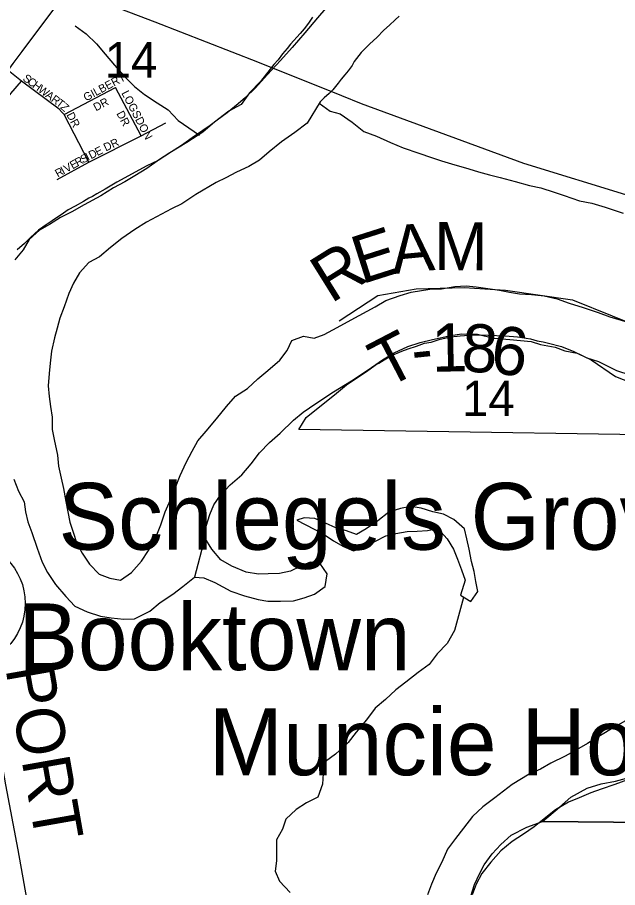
# Model space of a CAD drawing. Extents: x 1588073 to 2013523, y 1090242 to 1357120.
# Drawn here: x 1801898 to 1805645, y 1233367 to 1238801 of the extents above; entities that cross this region are included whole.
import ezdxf

# ---------------------------------------------------------------- set-up
doc = ezdxf.new("R2010")
doc.units = 0
for name, color, linetype in [('GM_X_County_Road', 7, 'Continuous'), ('GM_X_County_Road_Text', 7, 'Continuous'), ('GM_X_Interstate_Route', 7, 'Continuous'), ('GM_X_Major_River', 7, 'Continuous'), ('GM_X_Minor_River', 7, 'Continuous'), ('GM_X_Section', 7, 'Continuous'), ('GM_X_Section_Text', 7, 'Continuous'), ('GM_X_State_Route', 7, 'Continuous'), ('GM_X_Township_Road', 7, 'Continuous'), ('GM_X_Township_Road_Text', 7, 'Continuous'), ('GM_X_Township_Subdivision', 7, 'Continuous'), ('GM_X_Township_Subdivision_Text', 7, 'Continuous'), ('GM_X_Unincorporated', 7, 'Continuous'), ('GM_X_Unincorporated_Text', 7, 'Continuous')]:
    doc.layers.add(name, color=color, linetype=linetype)

msp = doc.modelspace()

# ---------------------------------------------------------------- linework, layer by layer
at = {"layer": 'GM_X_County_Road'}
for points in [[(1801278.3, 1237540.5), (1801476.7, 1237816.7), (1801857.4, 1238326), (1801923.8, 1238403.2), (1801839.7, 1238469.3)], [(1802090.5, 1232551.8), (1801902.1, 1233602.3), (1801826.4, 1234009.2), (1801770.7, 1234309.1), (1801713.5, 1234650.5), (1801537.5, 1235644.9), (1801253.4, 1237221.4), (1801246, 1237308.3), (1801251, 1237387.8), (1801278.3, 1237540.5)]]:
    msp.add_lwpolyline(points, dxfattribs=at)
at = {"layer": 'GM_X_Interstate_Route'}
for points in [[(1802220, 1238978.5), (1802756.8, 1238772.7), (1803397.5, 1238524.1), (1803921.3, 1238312.7)], [(1803921.3, 1238312.7), (1804043.4, 1238263.4), (1805058.6, 1237889.5), (1806385.8, 1237483.6), (1807153.2, 1237292.6), (1807255.1, 1237267), (1809826, 1236635.8), (1811204.6, 1236296.8), (1811922.8, 1236120.9), (1812389.9, 1236007.7), (1815154.9, 1235335.1), (1815934.8, 1235141.8), (1817359, 1234792.9), (1818064, 1234608.7), (1818464, 1234495.1), (1818935.1, 1234349.5), (1819197.3, 1234267.7)]]:
    msp.add_lwpolyline(points, dxfattribs=at)
at = {"layer": 'GM_X_Major_River'}
msp.add_line((1803067.9, 1235551.4), (1803003, 1235306.4), dxfattribs=at)
for points in [[(1803740.1, 1238801.8), (1803715.3, 1238764.1), (1803688.5, 1238728.5), (1803663.9, 1238700.8), (1803602.5, 1238633.6), (1803581.9, 1238605.8), (1803553.2, 1238572.2), (1803526.4, 1238536.6), (1803499.8, 1238506.9)], [(1804280.7, 1238807.7), (1804256.2, 1238786.1), (1804221.4, 1238752.6), (1804184.7, 1238721.1), (1804141.7, 1238675.7), (1804098.8, 1238636.3), (1804068.1, 1238604.7), (1804043.6, 1238581.1), (1804000.4, 1238525.6), (1803987.9, 1238499.7), (1803963.2, 1238468), (1803942.7, 1238442.3), (1803920.1, 1238414.6), (1803901.6, 1238390.8), (1803866.7, 1238349.2), (1803844.2, 1238325.6), (1803813.5, 1238298), (1803789, 1238274.3)], [(1803499.8, 1238506.9), (1803415.5, 1238400), (1803347.9, 1238328.9), (1803294.4, 1238257.5), (1803217.3, 1238214.8), (1803127.7, 1238146.1), (1803056.2, 1238083.1), (1802956.7, 1238018.7), (1802849, 1237954.4), (1802786, 1237913.4), (1802706.6, 1237856.6), (1802631.5, 1237811.8), (1802568.6, 1237774.8), (1802497.5, 1237735.9), (1802418.3, 1237687.2), (1802314.9, 1237630.8), (1802237.7, 1237586.1), (1802166.8, 1237551.2), (1802097.7, 1237508.3), (1802036.8, 1237471.3), (1801971.4, 1237414.2), (1801934.1, 1237348.6), (1801882.8, 1237287.3)], [(1803789, 1238274.3), (1803706.2, 1238139.2), (1803630.9, 1238082.4), (1803547.5, 1238023.6), (1803470, 1237960.8), (1803408.8, 1237909.7), (1803341.8, 1237870.7), (1803266.8, 1237834), (1803199.9, 1237799.1), (1803139.1, 1237770.1), (1803011.2, 1237694.1), (1802923.8, 1237637.4), (1802860.9, 1237604.5), (1802704.8, 1237523), (1802631.6, 1237476.1), (1802550.2, 1237419.4), (1802478.9, 1237364.4), (1802409.6, 1237305.5), (1802344.7, 1237270.5), (1802285.2, 1237205.3), (1802247.9, 1237141.7), (1802218.7, 1237075.9), (1802189.1, 1236994.1), (1802163.7, 1236922.2), (1802146.5, 1236860.2), (1802129.4, 1236800.2), (1802111.8, 1236716.1), (1802102.5, 1236641.9), (1802095.3, 1236577.8), (1802089.9, 1236499.5), (1802096.8, 1236433), (1802103.7, 1236370.6), (1802114.6, 1236304.1), (1802115.3, 1236227.7), (1802128.2, 1236165.1), (1802148.6, 1236066.3), (1802155.4, 1235997.8), (1802170.2, 1235923.1), (1802185.1, 1235858.6), (1802199.7, 1235777.9), (1802225.6, 1235648.8), (1802246.6, 1235586.1), (1802267.6, 1235521.3), (1802302.6, 1235456.4), (1802347.6, 1235387.2), (1802408.7, 1235323.7), (1802474.6, 1235300.4), (1802540.7, 1235287.1), (1802609.9, 1235334), (1802673.4, 1235405.2), (1802716.8, 1235472.7), (1802760.3, 1235548.2), (1802793.9, 1235632), (1802819.5, 1235713.9), (1802853, 1235787.7), (1802882.4, 1235861.5), (1802913.9, 1235941.3), (1802951.5, 1236021), (1802988.9, 1236092.6), (1803024.2, 1236156.3), (1803075.5, 1236217.6), (1803141.2, 1236294.8), (1803202.9, 1236372), (1803260.2, 1236435.2), (1803335.4, 1236484), (1803398.8, 1236543.1), (1803462, 1236596.2), (1803535.5, 1236661.2), (1803582.7, 1236720.6), (1803612, 1236784.3), (1803684.8, 1236811.1), (1803750.9, 1236797.8), (1803813.6, 1236820.7), (1803894.7, 1236865.4), (1803959.7, 1236900.4), (1804030.7, 1236939.2), (1804132.1, 1236993.6), (1804199.1, 1237032.5), (1804288.1, 1237065), (1804356.8, 1237085.8), (1804473.6, 1237103.7), (1804546, 1237106.4), (1804628.6, 1237120.9), (1804699, 1237123.6), (1804761.2, 1237118.4), (1804907.5, 1237097.6), (1804969.6, 1237084.3), (1805031.7, 1237075.1), (1805108, 1237069.7), (1805186.2, 1237062.1), (1805268.2, 1237042.5), (1805342.1, 1237017), (1805430, 1236989.2), (1805523.9, 1236957.3), (1805595.8, 1236931.8), (1805703.7, 1236899.6)], [(1803067.9, 1235551.4), (1803077.1, 1235624.7), (1803098.5, 1235696.6), (1803123.7, 1235756.4), (1803164.9, 1235818), (1803226.3, 1235881.1), (1803299.8, 1235944.1), (1803357.3, 1236013.3), (1803408.7, 1236082.7), (1803472.1, 1236145.8), (1803537.5, 1236204.9), (1803621.3, 1236285.7), (1803682.4, 1236334.8), (1803761.8, 1236389.6), (1803871.5, 1236461.9), (1803983.3, 1236532.1), (1804087, 1236600.5), (1804176.5, 1236663.1), (1804249.6, 1236706), (1804334.7, 1236746.6), (1804413.5, 1236771.2), (1804490.2, 1236789.9), (1804603.1, 1236813.9), (1804669.6, 1236824.7), (1804770.1, 1236822.8), (1804872.1, 1236798.8), (1804972.4, 1236788.8), (1805104.8, 1236776.3), (1805164.8, 1236759.1), (1805254.9, 1236741.3), (1805316.7, 1236718), (1805392.9, 1236704.5), (1805452.6, 1236675.2), (1805526.6, 1236651.8), (1805638.1, 1236595.4), (1805722, 1236569.7)], [(1801874.7, 1235916.7), (1801905.5, 1235841.7), (1801940.5, 1235776.7), (1801949.5, 1235714.3), (1801962.4, 1235651.7), (1801987.4, 1235584.9), (1802021.8, 1235485.8), (1802052.4, 1235398.8), (1802085.4, 1235333.8), (1802136.4, 1235260.5), (1802199.3, 1235185), (1802256.5, 1235123.6), (1802334.3, 1235090), (1802416.2, 1235062.3), (1802482.3, 1235051), (1802562.5, 1235043.4), (1802628.9, 1235046.2), (1802724.1, 1235092.7), (1802789.4, 1235147.7), (1802868.7, 1235200.5), (1802929.8, 1235247.6), (1803003, 1235306.4)], [(1803110.8, 1235481.3), (1803067.8, 1235550.5), (1803067.9, 1235551.4)], [(1803003, 1235306.4), (1803061.4, 1235301.4), (1803131.2, 1235271.9), (1803230.7, 1235217.8), (1803316.6, 1235190), (1803400.6, 1235166.3), (1803460.7, 1235155.1), (1803541, 1235155.6), (1803621.5, 1235158.1), (1803688.1, 1235177), (1803752.8, 1235199.9), (1803819.9, 1235246.9), (1803831.4, 1235327), (1803786.3, 1235392.2), (1803726.2, 1235399.4), (1803663.4, 1235372.4), (1803602.6, 1235343.4), (1803534, 1235328.6), (1803463.7, 1235325.9), (1803403.4, 1235325.1), (1803327.2, 1235336.6), (1803237.5, 1235374.4), (1803167.8, 1235413.9), (1803110.8, 1235481.3)], [(1805728.4, 1234427), (1805628.9, 1234370.6), (1805527.4, 1234310.2), (1805456.3, 1234267.3)], [(1805456.3, 1234267.3), (1805389.3, 1234228.4), (1805318.3, 1234187.5), (1805229.1, 1234145), (1805164.1, 1234106), (1805093.3, 1234075.2), (1804987.6, 1234010.9), (1804879.7, 1233928.5), (1804804.3, 1233871.6), (1804739, 1233810.6), (1804683.4, 1233739.2), (1804634.1, 1233673.8), (1804582.6, 1233606.5), (1804547.1, 1233526.8), (1804511.7, 1233457.1), (1804482.4, 1233389.3), (1804459.1, 1233321.4)], [(1805707.5, 1234039.5), (1805628.6, 1234010.8), (1805541.7, 1233982.3), (1805479, 1233959.4), (1805406.1, 1233928.6), (1805339.3, 1233901.7), (1805258.1, 1233853), (1805197, 1233805.9), (1805123.6, 1233747), (1805058.5, 1233700), (1804987.4, 1233655.1), (1804916, 1233596.2), (1804854.5, 1233527), (1804797, 1233455.7), (1804761.6, 1233388), (1804736.4, 1233322.2)]]:
    msp.add_lwpolyline(points, dxfattribs=at)
at = {"layer": 'GM_X_Minor_River'}
for points in [[(1802258.3, 1238747.5), (1802328.1, 1238698.8), (1802391.7, 1238636), (1802445.3, 1238571.4), (1802504.9, 1238502.7), (1802562.5, 1238436), (1802628.2, 1238369.2), (1802691.9, 1238318.5), (1802769.6, 1238267.7), (1802839.4, 1238223), (1802901, 1238156.2), (1803035.3, 1238064.8)], [(1803781.2, 1238265.3), (1803850.9, 1238214.6), (1803912.9, 1238198), (1803988.7, 1238147.2), (1804060.3, 1238088.4), (1804140.3, 1238059.7), (1804228.1, 1238018.8), (1804306, 1237986.1), (1804403.9, 1237953.1), (1804483.8, 1237926.4), (1804545.8, 1237905.8), (1804607.7, 1237887.2), (1804715.7, 1237854.2), (1804777.6, 1237835.6), (1804845.6, 1237817), (1804911.6, 1237800.4), (1805005.5, 1237775.6), (1805095.5, 1237750.7), (1805165.5, 1237736.1), (1805249.4, 1237709.3), (1805311.4, 1237688.8), (1805407.3, 1237655.8), (1805483.3, 1237641.2), (1805567.3, 1237616.4), (1805679.2, 1237579.3)], [(1804761.1, 1235279.4), (1804749.5, 1235341.7), (1804733.9, 1235404.1), (1804718.5, 1235480.4), (1804704.9, 1235544.8), (1804689.3, 1235607.1), (1804621.7, 1235665.8), (1804557.8, 1235698.5), (1804491.8, 1235713.1), (1804417.9, 1235735.8), (1804353.8, 1235746.3), (1804289.6, 1235734.8), (1804217.4, 1235711.3), (1804148.9, 1235657.7), (1804076.4, 1235608.2), (1804014, 1235572.6), (1803952.1, 1235595.1), (1803886.2, 1235613.8), (1803822.3, 1235642.4), (1803754.4, 1235671), (1803688.3, 1235675.6), (1803642.1, 1235661.7)], [(1803642.1, 1235661.7), (1803807.8, 1235576.3), (1803871.5, 1235531.6), (1803933.4, 1235497), (1803997.3, 1235470.4), (1804071.6, 1235497.8), (1804133.9, 1235529.4), (1804198.3, 1235563), (1804260.5, 1235578.6), (1804330.7, 1235590), (1804392.8, 1235593.5), (1804458.9, 1235597), (1804523.1, 1235608.5), (1804580.7, 1235545.8), (1804620.3, 1235481.2), (1804645.9, 1235418.8), (1804671.5, 1235352.4), (1804693, 1235286), (1804664.3, 1235193.9), (1804728.1, 1235153.3), (1804772.6, 1235215.1), (1804761.1, 1235279.4)], [(1804683.8, 1235179.6), (1804626.7, 1234973.5), (1804582, 1234891.6), (1804519.4, 1234825.9), (1804468.9, 1234760.1), (1804400.4, 1234710.5), (1804323.8, 1234649), (1804261.4, 1234601.3), (1804196.9, 1234541.7), (1804132.4, 1234488), (1804077.8, 1234414.2), (1804013.1, 1234338.5), (1803962.6, 1234272.7), (1803883.9, 1234201.1), (1803821.5, 1234155.5), (1803806.9, 1234079.4), (1803802.4, 1234013.2), (1803773.8, 1233931.2), (1803703.4, 1233895.6), (1803639, 1233854), (1803574.5, 1233794.4), (1803552, 1233732.4), (1803515.5, 1233666.4), (1803515, 1233600.2), (1803516.5, 1233534), (1803508, 1233469.9), (1803533.6, 1233407.4), (1803601.2, 1233336.7)]]:
    msp.add_lwpolyline(points, dxfattribs=at)
at = {"layer": 'GM_X_Section'}
for points in [[(1803824.1, 1238859.2), (1803771.7, 1238797.5), (1803693.1, 1238703.9), (1803612.4, 1238612.4), (1803539.9, 1238530.8), (1803459.3, 1238443.2), (1803382.7, 1238359.7), (1803322.3, 1238300), (1803276, 1238260.2), (1803207.6, 1238204.6), (1803145.3, 1238159), (1803101.1, 1238125.2), (1803054.9, 1238093.5), (1802988.6, 1238047.9), (1802936.3, 1238010.2), (1802900.1, 1237986.4), (1802859.9, 1237960.6), (1802777.6, 1237907.1), (1802705.3, 1237873.5), (1802655.1, 1237847.8), (1802590.9, 1237812.2), (1802518.6, 1237772.6), (1802446.3, 1237729.1), (1802394.1, 1237699.4), (1802365.9, 1237681.5), (1802343.9, 1237671.7), (1802309.7, 1237651.9), (1802259.5, 1237622.2), (1802215.3, 1237598.4), (1802185.2, 1237578.6), (1802114.8, 1237531), (1802076.6, 1237505.2), (1802030.4, 1237471.5), (1801980.1, 1237425.8), (1801941.9, 1237388), (1801895.6, 1237350.2)], [(1806595.2, 1236182.5), (1803655.7, 1236226.7), (1803700.2, 1236302.5), (1803889.2, 1236455.4), (1803953.6, 1236507), (1804078.2, 1236590.3), (1804132.4, 1236630), (1804154.5, 1236641.8), (1804188.7, 1236663.6), (1804228.9, 1236687.4), (1804297.1, 1236717), (1804337.2, 1236730.8), (1804389.3, 1236748.4), (1804439.5, 1236766.2), (1804481.5, 1236773.9), (1804537.7, 1236791.6), (1804603.8, 1236807.1), (1804661.9, 1236812.8), (1804744, 1236818.3), (1804838, 1236815.7), (1804944.1, 1236813.1), (1805020.1, 1236806.6), (1805102.1, 1236794.1), (1805144, 1236781.8), (1805180, 1236775.6), (1805214, 1236767.3), (1805293.9, 1236744.9), (1805371.7, 1236714.3), (1805479.5, 1236663.6), (1805632.9, 1236558.6), (1805726.8, 1236522)], [(1804728.3, 1233314.3), (1804752.7, 1233386.2), (1804783.2, 1233454), (1804811.5, 1233509.9), (1804862, 1233577.6), (1804916.4, 1233637.3), (1804980.8, 1233695), (1805079.1, 1233744.4), (1805175.4, 1233779.8), (1806952.5, 1233763.5)]]:
    msp.add_lwpolyline(points, dxfattribs=at)
msp.add_lwpolyline([(1805175.4, 1233779.8), (1805281.8, 1233869.5), (1805352.8, 1233932.6), (1805455.3, 1233987.8), (1805542, 1234015.4), (1805632.7, 1234031.1), (1805747, 1234062.7), (1805888.9, 1234090.3), (1806007.2, 1234090.3), (1806160.9, 1234098.1), (1806255.6, 1234078.4), (1806354.1, 1234046.9), (1806444.8, 1233999.6), (1806555.2, 1233956.2), (1806634, 1233905), (1806823.2, 1233818.2), (1806952.5, 1233763.5)], close=True, dxfattribs=at)
at = {"layer": 'GM_X_State_Route'}
for points in [[(1801927.7, 1238587), (1802220, 1238978.5)], [(1801600.3, 1238154.2), (1801839.7, 1238469.3), (1801872.1, 1238512.5), (1801927.7, 1238587)]]:
    msp.add_lwpolyline(points, dxfattribs=at)
at = {"layer": 'GM_X_Township_Road'}
msp.add_lwpolyline([(1803906.1, 1236906.5), (1804147.4, 1237063.9), (1804386.9, 1237106.6), (1804686.3, 1237114.3), (1804945.1, 1237096.5), (1805364.1, 1237038.1), (1806354.6, 1236637.5), (1806843.7, 1236427.3), (1807259.9, 1236167.8)], dxfattribs=at)
at = {"layer": 'GM_X_Township_Subdivision'}
for points in [[(1802188.4, 1238195.6), (1802177, 1238207.1), (1802158.4, 1238226.9), (1801923.8, 1238403.2)], [(1802190.7, 1238193.4), (1802509.6, 1238363.5)], [(1802671, 1238061.8), (1802509.6, 1238363.5)], [(1802343.3, 1237896.7), (1802190.7, 1238193.4), (1802188.4, 1238195.6)], [(1802145.9, 1237788.7), (1802343.3, 1237896.7), (1802671, 1238061.8), (1802825, 1238141.3)]]:
    msp.add_lwpolyline(points, dxfattribs=at)
at = {"layer": 'GM_X_Unincorporated'}
msp.add_circle((1801553.9, 1235142), 392.8, dxfattribs=at)

# ---------------------------------------------------------------- texts
at = {"layer": 'GM_X_County_Road_Text'}
msp.add_text('PORT', height=300, rotation=280.0198, dxfattribs=at).set_placement((1801822.6, 1234735))
at = {"layer": 'GM_X_Section_Text'}
for p in [(1802443, 1238425.1), (1804673.8, 1236310.9)]:
    msp.add_text('14', height=221, rotation=0, dxfattribs=at).set_placement(p)
at = {"layer": 'GM_X_Township_Road_Text'}
for s, rotation, p in [('A', 5.5787, (1804243.9, 1237197.8)), ('M', 359.681, (1804498.5, 1237223.1)), ('E', 17.6652, (1804046.4, 1237133)), ('R', 31.9524, (1803855.2, 1237010.9)), ('1', 1.2439, (1804486.7, 1236587.2)), ('8', 356.7301, (1804665.2, 1236591.3)), ('6', 353.7954, (1804845.6, 1236581.1)), ('T', 27.508, (1804200, 1236479.6)), ('-', 5.998, (1804370.7, 1236574.8))]:
    msp.add_text(s, height=300, rotation=rotation, dxfattribs=at).set_placement(p)
at = {"layer": 'GM_X_Township_Subdivision_Text'}
for s, rotation, p in [('S', 323.4362, (1801927.2, 1238410.9)), ('GILBERT', 28.2997, (1802326.4, 1238275.2)), ('C', 323.4353, (1801955.5, 1238390)), ('H', 323.4428, (1801987.3, 1238366.4)), ('W', 323.4361, (1802022.6, 1238340.2)), ('A', 323.4271, (1802068.6, 1238306.1)), ('LOGSDON', 297.3495, (1802546, 1238328.5)), ('R', 323.4519, (1802103.9, 1238279.9)), ('T', 322.2448, (1802135.5, 1238256.5)), ('DR', 27.8967, (1802388.2, 1238213.3)), ('Z', 316.7778, (1802162.4, 1238235.7)), ('DR', 297.9067, (1802514.7, 1238200.7)), ('DR', 297.8914, (1802202.7, 1238192.2)), ('DR', 25.1968, (1802450, 1237963.1)), ('S', 28.7282, (1802307.8, 1237887.8)), ('I', 27.4449, (1802338.4, 1237904.6)), ('D', 26.653, (1802357.7, 1237914.7)), ('E', 26.5406, (1802397, 1237934.4)), ('V', 29.1612, (1802204.1, 1237830)), ('E', 29.1316, (1802242.5, 1237851.4)), ('R', 29.1728, (1802273.3, 1237868.6)), ('R', 29.1395, (1802150.2, 1237800)), ('I', 29.1531, (1802184.8, 1237819.3))]:
    msp.add_text(s, height=50, rotation=rotation, dxfattribs=at).set_placement(p)
at = {"layer": 'GM_X_Unincorporated_Text'}
for s, p in [('Schlegels Grove', (1802154.8, 1235477.1)), ('Booktown', (1801904, 1234724.8)), ('Muncie Hollow', (1803092, 1234069.1))]:
    msp.add_text(s, height=417, rotation=0, dxfattribs=at).set_placement(p)

doc.saveas('drawing.dxf')
